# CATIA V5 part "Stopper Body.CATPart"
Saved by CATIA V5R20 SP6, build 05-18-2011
Part number: Stopper Body
Bounding box of the stored display mesh (mm): x 0 to 7, y -3.5 to 3.5, z -10 to 10
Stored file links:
  E:\#03 University\#02 영남 이공대\#01 2021\#02 여름 방학\#01 Documents\K-Move Page02 ASD02\Stopper Body.CATPart

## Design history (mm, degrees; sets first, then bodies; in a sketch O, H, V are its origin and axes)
Set1 "Reference Data"
  Point1 "Center Point": (0, 0, 0)
  Plane1 "Plane.1(X Dir = 7mm)": type Offset, RefPlane yz-plane, Offset 7
Body1 (main body)
  Body2
    Sketch1 on yz-plane, origin (0, 0, 0), H (0, 1, 0), V (0, 0, 1)
      line L1 (3.5, 10) -> (3.5, -10)
      line L2 (3.5, -10) -> (-3.5, -10)
      line L3 (-3.5, -10) -> (-3.5, 10)
      line L4 (-3.5, 10) -> (3.5, 10)
      circle A1 centre (0, 7.5) radius 1.5
      point P5 (0, 7.5)
      point P6 (0, -7.5)
      circle A2 centre (0, -7.5) radius 1.5
      distance L3 L1 = 7
      distance L4 L2 = 20
      radius A1 = 1.5
      distance P5 P6 = 15
      vertical: L1 V, L3 V
      horizontal: L2 H, L4 H
      equidistance: L1 L3 O, L2 L4 O
      coincidence: P5 V
      symmetry: A1 A2 H
    Pad1: profile Sketch1, direction (1, 0, 0), up to Plane1
  Assemble1: tool Body2
  Body3 "Hole Body"
    Sketch2 on zx-plane, origin (0, 0, 0), H (-1, 0, 0), V (0, 0, 1)
      circle A1 centre (-7, 0) radius 4
      point P1 (-7, 0)
      reference intersected line E1 through (-7, 0) direction (0, -1) from Plane1
      radius A1 = 4
      coincidence: P1 H, P1 E1
    Pad2: profile Sketch2, direction (0, 1, 0), length 7, mirrored extent
  Remove1: tool Body3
